(* LS Electric XG5000 project: XMC_AC_Drive_Ctrl_FB *)
(* PLC LSPLC *)
(* module base 0 slot 0: Input/Output Module:XMC-DN24 (DC 24V Input 8Points/TR output 16Points) *)
(* module base 0 slot 1: Internal Analog Input/Output:XMF-AH04E (A/D voltage/current 2 channels, D/A voltage 2 channels) *)
(* task Periodic Task: Kind=2 *)
(* task Initialization Task: Kind=1 *)
(* task NC Program: Kind=6 *)

FUNCTION_BLOCK XMC_AC_Drive_Ctrl_FB
(* This funciton block is used to provide ease of use for controlling EtherCAT AC drives with the XMC *)
VAR_IN_OUT
    Axis : UINT; (* Axis number of the AC drive. *)
END_VAR
VAR_INPUT
    Enable_Drive : BOOL; (* 0: Disable the drive;  1: Enable drive for operation / Motion will resume when drive is re-enabled. *)
    Quick_Stop : BOOL; (* 0: Motion not stopped;  1: Quick Stop the drive. / Motion will continue when reset back to 0. *)
    Change_Velocity : BOOL; (* Will change AC drive velocity on rising edge. *)
    Target_Velocity : INT; (* Target velocity of the AC drive in RPM. *)
    Reset_Fault : BOOL; (* Used to reset a fault *)
END_VAR
VAR_OUTPUT
    Drive_Enabled : BOOL; (* Status that the drive is Enabled *)
    Current_Velocity : INT; (* Current speed of the AC drive in RPM *)
    Drive_Faulted : BOOL; (* Status that the Drive is faulted *)
END_VAR
VAR CONSTANT
    Fault_Reaction_Active : USINT := 70; (* State status of Fault reaction active. *)
    Fault_State : USINT := 60; (* State status of Drive fault *)
    Not_Ready_To_Switch_On : USINT := 0; (* State status for Not Ready to switch on *)
    Operation_Enabled : USINT := 40; (* State status of Operation enabled *)
    Quick_Stop_Active : USINT := 50; (* State status of Quick stop active *)
    Ready_To_Switch_On : USINT := 20; (* State status of Ready to Switch On *)
    Switched_On : USINT := 30; (* State status of Switched on *)
    Switch_On_Disabled : USINT := 10; (* State status of Switch on disabled *)
END_VAR
VAR
    Previous_Change_Velocity : BOOL; (* history storage for change in velocity command *)
    Read_Status1 : LS_INVERTERSTATUS1; (* local function block for reading AC drive status *)
    Read_Status2 : LS_INVERTERSTATUS2; (* local funciton block for reading AC drive status *)
    Read_Velocity : LS_INVERTERREADVEL; (* local funciton block for reading drive velocity *)
    State : USINT := 0; (* State variable for controlling the AC drive *)
    Write_Control_Word : LS_INVERTERCONTROL; (* local function block for writing control word to the AC drive *)
    Write_Velocity : LS_INVERTERWRITEVEL; (* local function block for writing drive velocity *)
END_VAR
(* 
AutomationDirect.com has provided this code for convenience. This sample code is provided "as-is" with no expressed or implied warranty. 
 If the end user includes any of the sample code (in whole or part), it is the user's responsibility to completely modify, integrate, and test any code to ensure it meets all system and 
 safety requirements for the intended application or system.
 *)
 
 //If AC drive is faulted then move state machine to faulted state
 IF (Drive_Faulted) THEN
 	State := Fault_State;
 END_IF;	
 
 //Change previous velocity storage state if command to change velocity is set to FALSE
 IF (Change_Velocity = FALSE) THEN
 	Previous_Change_Velocity := FALSE;
 	Write_Velocity.Execute := FALSE;
 END_IF;

//State Machine for AC Drive control
CASE State OF
	
	//Drive starts in Not ready to switch on.  Wait for Drive to be in Switch On Disabled.
	0:
		IF (Enable_Drive = TRUE) THEN   //(Read_Status1.SwOnDisable) THEN
			State := Switch_On_Disabled;
		END_IF;
		
	//Switch On Disabled state	
	10: 	
		IF (Enable_Drive = TRUE) AND (Quick_Stop = FALSE) THEN
			Write_Control_Word.SwitchOn := FALSE;
			Write_Control_Word.VoltageEn := TRUE;
			Write_Control_Word.QuickStop := TRUE;
			Write_Control_Word.EnableOP := FALSE;
			
			Write_Control_Word.Execute :=  TRUE;
			
			//Move state machine to Ready To Switch On state
			IF (Read_Status1.RdySwitchOn) AND (Write_Control_Word.Done) THEN
				Write_Control_Word.Execute := FALSE;
				State :=  Ready_To_Switch_On;
			END_IF;
					
		ELSIF (Enable_Drive = FALSE) THEN		
			Write_Control_Word.SwitchOn := FALSE;
			Write_Control_Word.VoltageEn := FALSE;
			Write_Control_Word.QuickStop := FALSE;
			Write_Control_Word.EnableOP := FALSE;
			Write_Control_Word.Execute :=  FALSE;
		END_IF;	
		
	//Ready to Switch On State	
	20:
		IF (Enable_Drive = TRUE) THEN
			Write_Control_Word.SwitchOn := TRUE;
			Write_Control_Word.VoltageEn := TRUE;
			Write_Control_Word.QuickStop := TRUE;
			Write_Control_Word.EnableOP := FALSE;
			
			Write_Control_Word.Execute :=  TRUE;
			
			//Move state machine to Ready To Switch On state
			IF (Read_Status1.SwitchedOn) AND (Write_Control_Word.Done) THEN
				Write_Control_Word.Execute := FALSE;
				State :=  Switched_On;
			END_IF;
		
		
		ELSIF (Enable_Drive = FALSE) THEN
			Write_Control_Word.SwitchOn := FALSE;
			Write_Control_Word.VoltageEn := FALSE;
			Write_Control_Word.QuickStop := FALSE;
			Write_Control_Word.EnableOP := FALSE;
			
			Write_Control_Word.Execute :=  TRUE;
			
			//Move state machine to Quick Stop Active state
			IF (Read_Status1.SwOnDisable = FALSE) AND (Write_Control_Word.Done) THEN
				Write_Control_Word.Execute := FALSE;
				State :=  Switch_On_Disabled;
			END_IF;	
			
		END_IF;		
		
		
	//Switched On State	
	30:	
		IF (Enable_Drive = TRUE) THEN
			Write_Control_Word.SwitchOn := TRUE;
			Write_Control_Word.VoltageEn := TRUE;
			Write_Control_Word.QuickStop := TRUE;
			Write_Control_Word.EnableOP := TRUE;
			
			Write_Control_Word.Execute :=  TRUE;
			
			//Move state machine to Ready To Switch On state
			IF (Read_Status1.OpEn) AND (Write_Control_Word.Done) THEN
				Write_Control_Word.Execute := FALSE;
				State :=  Operation_Enabled;
			END_IF;
		
		ELSIF (Enable_Drive = FALSE) THEN
			Write_Control_Word.SwitchOn := FALSE;
			Write_Control_Word.VoltageEn := FALSE;
			Write_Control_Word.QuickStop := FALSE;
			Write_Control_Word.EnableOP := FALSE;
			
			Write_Control_Word.Execute :=  TRUE;
			
			//Move state machine to Quick Stop Active state
			IF (Read_Status1.SwOnDisable = FALSE) AND (Write_Control_Word.Done) THEN
				Write_Control_Word.Execute := FALSE;
				State :=  Switch_On_Disabled;
			END_IF;	
			
		END_IF;			
		
	//Operation Enabled state	
	40:		
		//disable the drive
		IF (Enable_Drive =  FALSE) THEN
			Write_Control_Word.SwitchOn := FALSE;
			Write_Control_Word.VoltageEn := FALSE;
			Write_Control_Word.QuickStop := FALSE;
			Write_Control_Word.EnableOP := FALSE;
			
			Write_Control_Word.Execute :=  TRUE;
			
			//Move state machine to Quick Stop Active state
			IF (Read_Status1.SwOnDisable = FALSE) AND (Write_Control_Word.Done) THEN
				Write_Control_Word.Execute := FALSE;
				State :=  Switch_On_Disabled;
			END_IF;
				
		//stop motion
		ELSIF (Quick_Stop =  TRUE) THEN
			Write_Control_Word.SwitchOn := TRUE;
			Write_Control_Word.VoltageEn := TRUE;
			Write_Control_Word.QuickStop := FALSE;
			Write_Control_Word.EnableOP := TRUE;
			
			Write_Control_Word.Execute :=  TRUE;
			
			//Move state machine to Quick Stop Active state
			IF (Read_Status2.QuickStop) AND (Write_Control_Word.Done) THEN
				Write_Control_Word.Execute := FALSE;
				State :=  Quick_Stop_Active;
			END_IF;
			
		//Change drive velocity	
		ELSIF (Change_Velocity = TRUE) AND (Previous_Change_Velocity = FALSE) THEN
			Write_Velocity.Execute := TRUE;	
			
			IF (Write_Velocity.Done) THEN
				Write_Velocity.Execute := FALSE;
				Previous_Change_Velocity := TRUE;
			END_IF;	

	
		END_IF; //end main if statement of Operation enable state
	
	//Quick Stop Active state
	50:
		//disable the drive
		IF (Quick_Stop =  FALSE) THEN
			Write_Control_Word.SwitchOn := FALSE;
			Write_Control_Word.VoltageEn := FALSE;
			Write_Control_Word.QuickStop := FALSE;
			Write_Control_Word.EnableOP := FALSE;
			
			Write_Control_Word.Execute :=  TRUE;
			
			//Move state machine to Quick Stop Active state
			IF (Read_Status1.SwOnDisable = TRUE) AND (Write_Control_Word.Done) THEN
				Write_Control_Word.Execute := FALSE;
				State :=  Switch_On_Disabled;
			END_IF;
		END_IF; //end main if in Quick stop active		
	
	//Fault state
	60:
		IF (Reset_Fault) THEN
			Write_Control_Word.SwitchOn := FALSE;
			Write_Control_Word.VoltageEn := FALSE;
			Write_Control_Word.QuickStop := FALSE;
			Write_Control_Word.EnableOP := FALSE;
			Write_Control_Word.FaultReset := TRUE;
			
			Write_Control_Word.Execute :=  TRUE;
			
			//Move state machine to Quick Stop Active state
			IF (Read_Status2.Fault = FALSE) AND (Write_Control_Word.Done) THEN
				Write_Control_Word.Execute := FALSE;
				Write_Control_Word.FaultReset := FALSE;
				State :=  Switch_On_Disabled;
			END_IF;
		END_IF;	
	
END_CASE; // end state machine



//local AC drive function block calls
Write_Control_Word(Execute:=Write_Control_Word.Execute, Axis:=Axis, SwitchOn:=Write_Control_Word.SwitchOn, VoltageEn:=Write_Control_Word.VoltageEn, QuickStop:=Write_Control_Word.QuickStop, EnableOP:=Write_Control_Word.EnableOP, EnableRamp:=Write_Control_Word.EnableRamp, UnlockRamp:=Write_Control_Word.UnlockRamp, ReferenceRamp:=Write_Control_Word.ReferenceRamp, FaultReset:=Write_Control_Word.FaultReset, Halt:=Write_Control_Word.Halt);
Write_Velocity(Execute:=Write_Velocity.Execute, Axis:=Axis, TargetVel:=Target_Velocity);

Read_Status1(Enable:=Enable_Drive, Axis:=Axis, OpEn=>Drive_Enabled);
Read_Status2(Enable:=Enable_Drive, Axis:=Axis, Fault=>Drive_Faulted);
Read_Velocity(Enable:=TRUE, Axis:=Axis,  ActualVel=>Current_Velocity);
END_FUNCTION_BLOCK

PROGRAM NewProgram (* task: Scan Program *)
VAR
    AC_Drive_INST : XMC_AC_Drive_Ctrl_FB; (* function block to control an AC drive over EtherCAT *)
    Axis1 : UINT; (* Axis variable for Axis 1 *)
    Change_Velocity : BOOL; (* Command to change AC drive velocity *)
    Connect_Busy : BOOL; (* busy status for LS_Conncet *)
    Connect_Error : BOOL; (* error status for LS_Connect *)
    Connect_ErrorID : WORD; (* error identification for LS_Connect *)
    Current_Velocity : INT; (* current Velocity of the AC drive *)
    Disconnect_Busy : BOOL; (* busy status for LS_Disconnect *)
    Disconnect_Error : BOOL; (* Error status for LS_Disconnect *)
    Disconnect_ErrorID : WORD; (* error identification for LS_DIsconnect *)
    Drive_Enabled : BOOL; (* Status that AC drive is enabled *)
    Drive_Faulted : BOOL; (* status that the AC drive is faulted *)
    ECAT_Connect : LS_CONNECT; (* function block to connect EtherCAT network *)
    ECAT_Disconnect : LS_DISCONNECT; (* function block to disconnect the EtherCAT network *)
    Enable_Drive : BOOL; (* enable the AC Drive *)
    Execute_Connect : BOOL; (* Execute the connection of EtherCAT network *)
    Execute_Disconnect : BOOL; (* execute LS_Disconnect *)
    Quick_Stop : BOOL; (* stop AC drive motion. Motion will resume when set to '0'. *)
    Reset_Fault : BOOL; (* Command to reset an AC drive fault *)
    Target_Velocity : INT; (* Velocity in RPM to set to AC drive *)
END_VAR

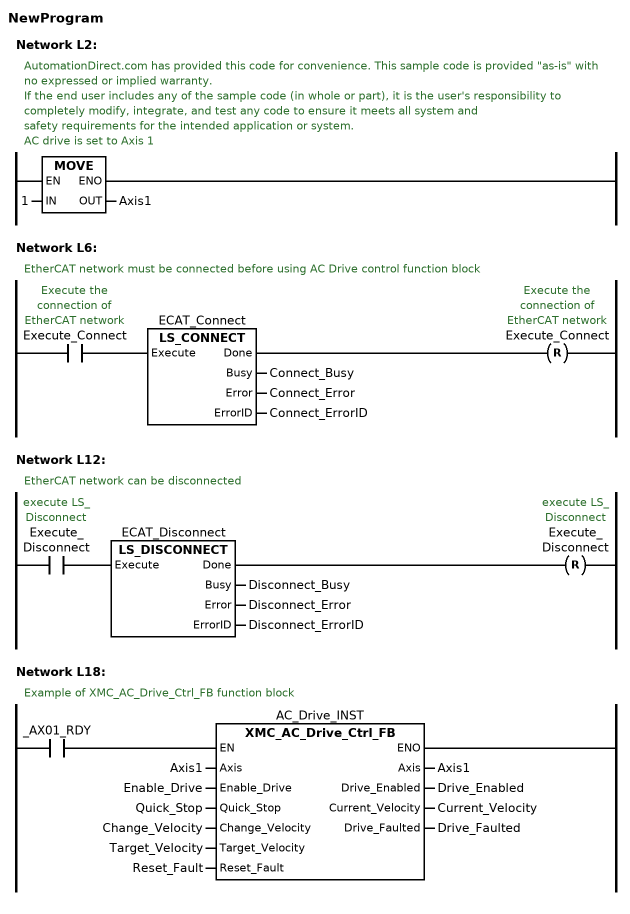
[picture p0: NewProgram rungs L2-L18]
(* AutomationDirect.com has provided this code for convenience. This sample code is provided "as-is" with no expressed or implied warranty. / If the end user includes any of the sample code (in whole or part), it is the user's responsibility to completely modify, integrate, and test any code to ensure it meets all system and / safety requirements for the intended application or system. *)
(* AC drive is set to Axis 1 *)
(* Rung L2 *)
Axis1 := 1;
(* EtherCAT network must be connected before using AC Drive control function block *)
(* Rung L6 *)
ECAT_Connect(Execute := Execute_Connect, Busy => Connect_Busy, Error => Connect_Error, ErrorID => Connect_ErrorID);
IF ECAT_Connect.Done THEN Execute_Connect := FALSE; END_IF;
(* EtherCAT network can be disconnected *)
(* Rung L12 *)
ECAT_Disconnect(Execute := Execute_Disconnect, Busy => Disconnect_Busy, Error => Disconnect_Error, ErrorID => Disconnect_ErrorID);
IF ECAT_Disconnect.Done THEN Execute_Disconnect := FALSE; END_IF;
(* Example of XMC_AC_Drive_Ctrl_FB function block *)
(* Rung L18 *)
IF _AX01_RDY THEN
    AC_Drive_INST(Axis := Axis1, Enable_Drive := Enable_Drive, Quick_Stop := Quick_Stop, Change_Velocity := Change_Velocity, Target_Velocity := Target_Velocity, Reset_Fault := Reset_Fault, Axis => Axis1, Drive_Enabled => Drive_Enabled, Current_Velocity => Current_Velocity, Drive_Faulted => Drive_Faulted);
END_IF;
END_PROGRAM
